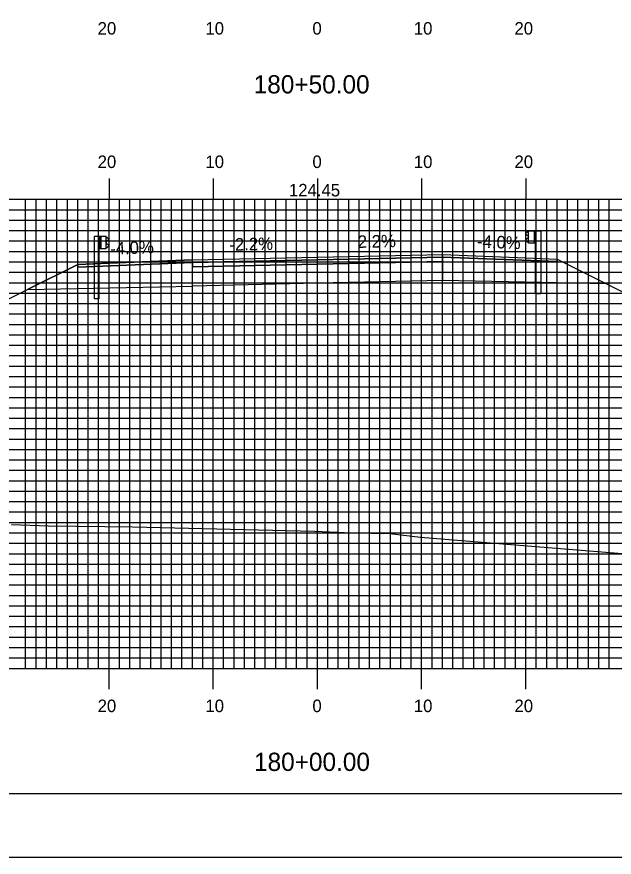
# Model space of a CAD drawing. Extents: x 1785795 to 1786139, y 442591 to 442811.
# Drawn here: x 1785932.2 to 1785989.5, y 442590.5 to 442671.2 of the extents above; entities that cross this region are included whole.
import ezdxf

# ---------------------------------------------------------------- set-up
doc = ezdxf.new("R2010")
doc.units = 0
for name, color, linetype in [('ANNOTATION', 7, 'Continuous'), ('BORDER', 7, 'Continuous'), ('D_Guardrail_Beam_Lt', 7, 'Continuous'), ('D_Guardrail_Beam_Rt', 7, 'Continuous'), ('D_Roadway_Centerline', 7, 'Continuous'), ('D_Roadway_Centerline_Text', 7, 'Continuous'), ('D_Roadway_Edge_Shoulder', 7, 'Continuous'), ('D_Roadway_Edge_TW', 7, 'Continuous'), ('D_Roadway_Pavement', 7, 'Continuous'), ('D_Roadway_SlopeLines', 7, 'Continuous'), ('D_Roadway_SubGrade', 7, 'Continuous'), ('H_V ANNOTATION', 7, 'Continuous'), ('MAJOR', 7, 'Continuous'), ('MINOR', 7, 'Continuous'), ('PLOT BOUNDARY', 7, 'Continuous'), ('S_Roadway_Centerline', 7, 'Continuous')]:
    doc.layers.add(name, color=color, linetype=linetype)

msp = doc.modelspace()

# ---------------------------------------------------------------- linework, layer by layer
at = {"layer": 'BORDER'}
msp.add_lwpolyline([(1785811.452, 442596.665), (1786131.452, 442596.665), (1786131.452, 442806.665), (1785811.452, 442806.665)], close=True, dxfattribs=at)
at = {"layer": 'D_Guardrail_Beam_Lt'}
for p, q in [((1785939.623, 442650.11), (1785939.623, 442644.11)), ((1785940.093, 442650.11), (1785939.623, 442650.11)), ((1785940.781, 442650.11), (1785940.093, 442650.11)), ((1785940.093, 442650.11), (1785940.093, 442648.943)), ((1785940.156, 442650.11), (1785940.156, 442648.943)), ((1785940.26, 442650.11), (1785940.26, 442648.943)), ((1785940.781, 442648.943), (1785940.781, 442650.11)), ((1785940.781, 442650.026), (1785940.855, 442650.012)), ((1785940.785, 442649.561), (1785940.785, 442649.491)), ((1785941.014, 442649.762), (1785940.819, 442649.626)), ((1785940.871, 442650.005), (1785941.014, 442649.905)), ((1785940.093, 442648.943), (1785940.781, 442648.943)), ((1785940.114, 442644.11), (1785940.114, 442648.943)), ((1785940.855, 442649.041), (1785940.781, 442649.026)), ((1785940.819, 442649.427), (1785941.014, 442649.291)), ((1785941.014, 442649.148), (1785940.871, 442649.048)), ((1785940.114, 442644.11), (1785939.623, 442644.11))]:
    msp.add_line(p, q, dxfattribs=at)
for centre, major_axis, start_param, end_param in [((1785940.864, 442649.561), (-0.0789, 0), 5.323254, 6.283185), ((1785940.864, 442649.491), (-0.0789, 0), 6.283185, 7.243116), ((1785940.847, 442649.971), (0.0417, 0), 0.959931, 1.376053), ((1785940.964, 442649.833), (0.0877, 0), 5.323254, 7.243116), ((1785940.847, 442649.082), (0.0417, 0), 4.907132, 5.323254), ((1785940.964, 442649.219), (0.0877, 0), 5.323254, 7.243116)]:
    msp.add_ellipse(centre, major_axis=major_axis, ratio=0.995501, start_param=start_param, end_param=end_param, dxfattribs=at)
at = {"layer": 'D_Guardrail_Beam_Rt'}
for p, q in [((1785981.233, 442650.533), (1785981.089, 442650.433)), ((1785981.089, 442650.29), (1785981.285, 442650.154)), ((1785981.323, 442650.554), (1785981.248, 442650.54)), ((1785981.323, 442650.638), (1785982.01, 442650.638)), ((1785981.323, 442649.471), (1785981.323, 442650.638)), ((1785981.843, 442650.638), (1785981.843, 442649.471)), ((1785981.948, 442650.638), (1785981.948, 442649.471)), ((1785982.01, 442650.638), (1785982.481, 442650.638)), ((1785982.01, 442650.638), (1785982.01, 442649.471)), ((1785982.481, 442650.638), (1785982.481, 442644.638)), ((1785981.285, 442649.955), (1785981.089, 442649.819)), ((1785981.089, 442649.676), (1785981.233, 442649.576)), ((1785981.248, 442649.569), (1785981.323, 442649.554)), ((1785981.318, 442650.089), (1785981.318, 442650.019)), ((1785982.01, 442649.471), (1785981.323, 442649.471)), ((1785981.989, 442644.638), (1785981.989, 442649.471)), ((1785981.989, 442644.638), (1785982.481, 442644.638))]:
    msp.add_line(p, q, dxfattribs=at)
for centre, major_axis, start_param, end_param in [((1785981.139, 442650.361), (-0.0877, 0), 5.323254, 7.243116), ((1785981.257, 442650.499), (-0.0417, 0), 4.907132, 5.323254), ((1785981.139, 442649.747), (-0.0877, 0), 5.323254, 7.243116), ((1785981.257, 442649.61), (-0.0417, 0), 0.959931, 1.376053), ((1785981.239, 442650.089), (0.0789, 0), 0, 0.959931), ((1785981.239, 442650.019), (0.0789, 0), 5.323254, 6.283185)]:
    msp.add_ellipse(centre, major_axis=major_axis, ratio=0.995501, start_param=start_param, end_param=end_param, dxfattribs=at)
at = {"layer": 'D_Roadway_Centerline'}
msp.add_lwpolyline([(1785891.131, 442623.946), (1785933.236, 442644.998), (1785938.052, 442647.406), (1785941.052, 442647.526), (1785949.052, 442647.846), (1785961.052, 442648.11), (1785973.052, 442648.374), (1785981.052, 442648.054), (1785984.052, 442647.934), (1785988.802, 442645.559), (1786043.1, 442618.41)], dxfattribs=at)
at = {"layer": 'D_Roadway_Edge_Shoulder'}
for points in [[(1785949.052, 442647.846), (1785941.052, 442647.526), (1785941.052, 442647.526), (1785938.052, 442647.406), (1785938.052, 442647.156), (1785949.052, 442647.596)], [(1785973.052, 442648.374), (1785981.052, 442648.054), (1785981.052, 442648.054), (1785984.052, 442647.934), (1785984.052, 442647.684), (1785973.052, 442648.124)]]:
    msp.add_lwpolyline(points, close=True, dxfattribs=at)
at = {"layer": 'D_Roadway_Edge_TW'}
msp.add_lwpolyline([(1785949.052, 442647.596), (1785949.052, 442647.846), (1785961.052, 442648.11), (1785973.052, 442648.374), (1785973.052, 442648.124), (1785961.052, 442647.86)], close=True, dxfattribs=at)
at = {"layer": 'D_Roadway_Pavement'}
msp.add_lwpolyline([(1785949.052, 442647.18), (1785949.052, 442647.596), (1785961.052, 442647.86), (1785973.052, 442648.124), (1785973.052, 442647.708), (1785961.052, 442647.444)], close=True, dxfattribs=at)
for points in [[(1785973.052, 442648.124), (1785973.052, 442647.708)], [(1785949.052, 442647.596), (1785949.052, 442647.18)]]:
    msp.add_lwpolyline(points, dxfattribs=at)
at = {"layer": 'D_Roadway_SlopeLines'}
for points in [[(1785984.052, 442647.934), (1786043.1, 442618.41)], [(1785938.052, 442647.406), (1785891.131, 442623.946)]]:
    msp.add_lwpolyline(points, dxfattribs=at)
at = {"layer": 'D_Roadway_SubGrade'}
for points in [[(1785949.052, 442645.346), (1785949.052, 442647.596), (1785949.052, 442647.18), (1785961.052, 442647.444), (1785973.052, 442647.708), (1785973.052, 442648.124), (1785973.052, 442645.874), (1785961.052, 442645.61)], [(1785973.052, 442647.708), (1785973.052, 442648.124), (1785984.052, 442647.684), (1785984.052, 442647.934), (1785988.802, 442645.559), (1785973.052, 442645.874)], [(1785949.052, 442647.18), (1785949.052, 442647.596), (1785938.052, 442647.156), (1785938.052, 442647.406), (1785933.236, 442644.998), (1785949.052, 442645.346)]]:
    msp.add_lwpolyline(points, close=True, dxfattribs=at)
at = {"layer": 'MAJOR'}
for p, q in [((1785941.052, 442655.669), (1785941.052, 442653.665)), ((1785951.052, 442655.669), (1785951.052, 442653.665)), ((1785961.052, 442655.669), (1785961.052, 442653.665)), ((1785971.052, 442655.669), (1785971.052, 442653.665)), ((1785981.052, 442655.669), (1785981.052, 442653.665)), ((1785821.052, 442653.665), (1786101.052, 442653.665)), ((1785821.052, 442653.665), (1786101.052, 442653.665)), ((1785941.052, 442608.665), (1785941.052, 442653.665)), ((1785951.052, 442608.665), (1785951.052, 442653.665)), ((1785961.052, 442608.665), (1785961.052, 442653.665)), ((1785971.052, 442608.665), (1785971.052, 442653.665)), ((1785981.052, 442608.665), (1785981.052, 442653.665)), ((1785821.052, 442648.665), (1786101.052, 442648.665)), ((1785821.052, 442643.665), (1786101.052, 442643.665)), ((1785821.052, 442638.665), (1786101.052, 442638.665)), ((1785821.052, 442633.665), (1786101.052, 442633.665)), ((1785821.052, 442628.665), (1786101.052, 442628.665)), ((1785821.052, 442623.665), (1786101.052, 442623.665)), ((1785821.052, 442618.665), (1786101.052, 442618.665)), ((1785821.052, 442613.665), (1786101.052, 442613.665)), ((1785821.052, 442608.665), (1786101.052, 442608.665)), ((1785821.052, 442608.665), (1786101.052, 442608.665)), ((1785941.052, 442606.661), (1785941.052, 442608.665)), ((1785951.052, 442606.661), (1785951.052, 442608.665)), ((1785961.052, 442606.661), (1785961.052, 442608.665)), ((1785971.052, 442606.661), (1785971.052, 442608.665)), ((1785981.052, 442606.661), (1785981.052, 442608.665))]:
    msp.add_line(p, q, dxfattribs=at)
at = {"layer": 'MINOR'}
for p, q in [((1785933.052, 442608.665), (1785933.052, 442653.665)), ((1785934.052, 442608.665), (1785934.052, 442653.665)), ((1785935.052, 442608.665), (1785935.052, 442653.665)), ((1785936.052, 442608.665), (1785936.052, 442653.665)), ((1785937.052, 442608.665), (1785937.052, 442653.665)), ((1785938.052, 442608.665), (1785938.052, 442653.665)), ((1785939.052, 442608.665), (1785939.052, 442653.665)), ((1785940.052, 442608.665), (1785940.052, 442653.665)), ((1785942.052, 442608.665), (1785942.052, 442653.665)), ((1785943.052, 442608.665), (1785943.052, 442653.665)), ((1785944.052, 442608.665), (1785944.052, 442653.665)), ((1785945.052, 442608.665), (1785945.052, 442653.665)), ((1785946.052, 442608.665), (1785946.052, 442653.665)), ((1785947.052, 442608.665), (1785947.052, 442653.665)), ((1785948.052, 442608.665), (1785948.052, 442653.665)), ((1785949.052, 442608.665), (1785949.052, 442653.665)), ((1785950.052, 442608.665), (1785950.052, 442653.665)), ((1785952.052, 442608.665), (1785952.052, 442653.665)), ((1785953.052, 442608.665), (1785953.052, 442653.665)), ((1785954.052, 442608.665), (1785954.052, 442653.665)), ((1785955.052, 442608.665), (1785955.052, 442653.665)), ((1785956.052, 442608.665), (1785956.052, 442653.665)), ((1785957.052, 442608.665), (1785957.052, 442653.665)), ((1785958.052, 442608.665), (1785958.052, 442653.665)), ((1785959.052, 442608.665), (1785959.052, 442653.665)), ((1785960.052, 442608.665), (1785960.052, 442653.665)), ((1785962.052, 442608.665), (1785962.052, 442653.665)), ((1785963.052, 442608.665), (1785963.052, 442653.665)), ((1785964.052, 442608.665), (1785964.052, 442653.665)), ((1785965.052, 442608.665), (1785965.052, 442653.665)), ((1785966.052, 442608.665), (1785966.052, 442653.665)), ((1785967.052, 442608.665), (1785967.052, 442653.665)), ((1785968.052, 442608.665), (1785968.052, 442653.665)), ((1785969.052, 442608.665), (1785969.052, 442653.665)), ((1785970.052, 442608.665), (1785970.052, 442653.665)), ((1785972.052, 442608.665), (1785972.052, 442653.665)), ((1785973.052, 442608.665), (1785973.052, 442653.665)), ((1785974.052, 442608.665), (1785974.052, 442653.665)), ((1785975.052, 442608.665), (1785975.052, 442653.665)), ((1785976.052, 442608.665), (1785976.052, 442653.665)), ((1785977.052, 442608.665), (1785977.052, 442653.665)), ((1785978.052, 442608.665), (1785978.052, 442653.665)), ((1785979.052, 442608.665), (1785979.052, 442653.665)), ((1785980.052, 442608.665), (1785980.052, 442653.665)), ((1785982.052, 442608.665), (1785982.052, 442653.665)), ((1785983.052, 442608.665), (1785983.052, 442653.665)), ((1785984.052, 442608.665), (1785984.052, 442653.665)), ((1785985.052, 442608.665), (1785985.052, 442653.665)), ((1785986.052, 442608.665), (1785986.052, 442653.665)), ((1785987.052, 442608.665), (1785987.052, 442653.665)), ((1785988.052, 442608.665), (1785988.052, 442653.665)), ((1785989.052, 442608.665), (1785989.052, 442653.665)), ((1785821.052, 442652.665), (1786101.052, 442652.665)), ((1785821.052, 442651.665), (1786101.052, 442651.665)), ((1785821.052, 442650.665), (1786101.052, 442650.665)), ((1785821.052, 442649.665), (1786101.052, 442649.665)), ((1785821.052, 442647.665), (1786101.052, 442647.665)), ((1785821.052, 442646.665), (1786101.052, 442646.665)), ((1785821.052, 442645.665), (1786101.052, 442645.665)), ((1785821.052, 442644.665), (1786101.052, 442644.665)), ((1785821.052, 442642.665), (1786101.052, 442642.665)), ((1785821.052, 442641.665), (1786101.052, 442641.665)), ((1785821.052, 442640.665), (1786101.052, 442640.665)), ((1785821.052, 442639.665), (1786101.052, 442639.665)), ((1785821.052, 442637.665), (1786101.052, 442637.665)), ((1785821.052, 442636.665), (1786101.052, 442636.665)), ((1785821.052, 442635.665), (1786101.052, 442635.665)), ((1785821.052, 442634.665), (1786101.052, 442634.665)), ((1785821.052, 442632.665), (1786101.052, 442632.665)), ((1785821.052, 442631.665), (1786101.052, 442631.665)), ((1785821.052, 442630.665), (1786101.052, 442630.665)), ((1785821.052, 442629.665), (1786101.052, 442629.665)), ((1785821.052, 442627.665), (1786101.052, 442627.665)), ((1785821.052, 442626.665), (1786101.052, 442626.665)), ((1785821.052, 442625.665), (1786101.052, 442625.665)), ((1785821.052, 442624.665), (1786101.052, 442624.665)), ((1785821.052, 442622.665), (1786101.052, 442622.665)), ((1785821.052, 442621.665), (1786101.052, 442621.665)), ((1785821.052, 442620.665), (1786101.052, 442620.665)), ((1785821.052, 442619.665), (1786101.052, 442619.665)), ((1785821.052, 442617.665), (1786101.052, 442617.665)), ((1785821.052, 442616.665), (1786101.052, 442616.665)), ((1785821.052, 442615.665), (1786101.052, 442615.665)), ((1785821.052, 442614.665), (1786101.052, 442614.665)), ((1785821.052, 442612.665), (1786101.052, 442612.665)), ((1785821.052, 442611.665), (1786101.052, 442611.665)), ((1785821.052, 442610.665), (1786101.052, 442610.665)), ((1785821.052, 442609.665), (1786101.052, 442609.665))]:
    msp.add_line(p, q, dxfattribs=at)
at = {"layer": 'PLOT BOUNDARY'}
msp.add_lwpolyline([(1785795.265, 442590.547), (1786135.265, 442590.547), (1786135.265, 442810.547), (1785795.265, 442810.547)], close=True, dxfattribs=at)
at = {"layer": 'S_Roadway_Centerline'}
msp.add_lwpolyline([(1785931.687, 442622.463), (1785935.233, 442622.339), (1785943.333, 442622.252), (1785960.761, 442621.827), (1785964.38, 442621.652), (1785968.016, 442621.596), (1785970.948, 442621.241), (1785989.921, 442619.719), (1785991.344, 442619.692), (1786002.271, 442619.738), (1786013.496, 442619.205), (1786014.533, 442619.194), (1786015.752, 442619.155), (1786025.541, 442618.852), (1786034.235, 442618.896), (1786037.443, 442618.861), (1786053.969, 442617.544), (1786059.798, 442617.477), (1786066.871, 442617.312), (1786072.22, 442617.329), (1786075.65, 442617.277), (1786095.174, 442616.762), (1786097.059, 442616.773), (1786101.052, 442616.957)], dxfattribs=at)

# ---------------------------------------------------------------- texts
at = {"layer": 'ANNOTATION'}
for s, rotation, p in [('2.2%', 1.2603, (1785964.932, 442648.996)), ('-4.0%', 2.29061, (1785941.184, 442648.333)), ('-2.2%', 1.2603, (1785952.611, 442648.725)), ('-4.0%', 357.70939, (1785976.343, 442649.044))]:
    msp.add_text(s, height=1.2, rotation=rotation, dxfattribs=at).set_placement(p)
at = {"layer": 'D_Roadway_Centerline'}
for s, p in [('C', (1785961.047, 442648.11)), ('L', (1785961.052, 442648.103))]:
    msp.add_text(s, height=0.0146, dxfattribs=at).set_placement(p)
at = {"layer": 'D_Roadway_Centerline_Text'}
msp.add_text('124.45', height=1.2, dxfattribs=at).set_placement((1785958.318, 442653.943))
at = {"layer": 'H_V ANNOTATION'}
for s, height, p in [('20', 1.2, (1785939.96, 442669.465)), ('10', 1.2, (1785950.302, 442669.465)), ('0', 1.2, (1785960.57, 442669.465)), ('10', 1.2, (1785970.302, 442669.465)), ('20', 1.2, (1785979.96, 442669.465)), ('180+50.00', 1.75, (1785954.934, 442663.821)), ('20', 1.2, (1785939.96, 442656.665)), ('10', 1.2, (1785950.302, 442656.665)), ('0', 1.2, (1785960.57, 442656.665)), ('10', 1.2, (1785970.302, 442656.665)), ('20', 1.2, (1785979.96, 442656.665)), ('20', 1.2, (1785939.96, 442604.465)), ('10', 1.2, (1785950.302, 442604.465)), ('0', 1.2, (1785960.57, 442604.465)), ('10', 1.2, (1785970.302, 442604.465)), ('20', 1.2, (1785979.96, 442604.465)), ('180+00.00', 1.75, (1785954.966, 442598.821))]:
    msp.add_text(s, height=height, dxfattribs=at).set_placement(p)

doc.saveas('drawing.dxf')
